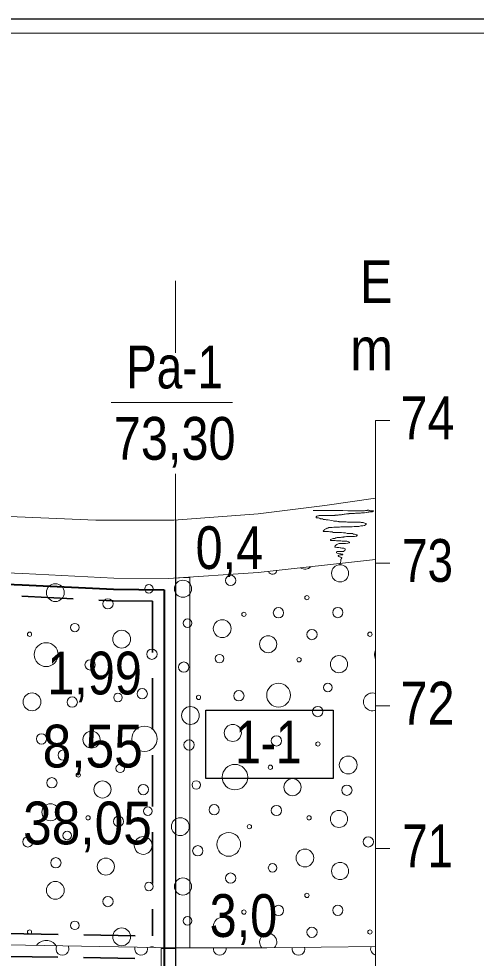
# Model space of a CAD drawing. Extents: x 640121 to 640955, y 6441885 to 6442246.
# Drawn here: x 640485.5 to 640517.6, y 6442180.3 to 6442246.2 of the extents above; entities that cross this region are included whole.
import ezdxf
from ezdxf.enums import TextEntityAlignment as Align

# ---------------------------------------------------------------- set-up
doc = ezdxf.new("R2010")
doc.units = 0
doc.header["$LTSCALE"] = 1.2
doc.linetypes.add('MEDIUM_DASHED', pattern=[4.5, 3, -1.5])
for name, color, linetype, lineweight in [('30', 7, 'Continuous', 13), ('31', 7, 'Continuous', 13), ('32', 7, 'Continuous', 13), ('33', 7, 'Continuous', 13), ('35', 7, 'Continuous', 35), ('40', 7, 'Continuous', 13), ('41', 7, 'Continuous', 13), ('42', 7, 'Continuous', 13), ('50', 7, 'Continuous', 13)]:
    doc.layers.add(name, color=color, linetype=linetype, lineweight=lineweight)

msp = doc.modelspace()

# ---------------------------------------------------------------- linework, layer by layer
at = {"layer": '30'}
for p, q in [((640510.5, 6442218), (640511.5, 6442218)), ((640510.5, 6442063), (640510.5, 6442218)), ((640510.5, 6442208), (640511.5, 6442208)), ((640510.5, 6442198), (640511.5, 6442198)), ((640510.5, 6442188), (640511.5, 6442188))]:
    msp.add_line(p, q, dxfattribs=at)
at = {"layer": '31'}
for points in [[(640362.7, 6442207.53), (640371.1, 6442207.66), (640378.91, 6442207.96), (640387.66, 6442208.39), (640395.09, 6442208.91), (640403.04, 6442209.13), (640410.1, 6442209.62), (640417.94, 6442210.22), (640426.11, 6442210.87), (640434.35, 6442211.6), (640443.55, 6442211.39), (640450.84, 6442211.31), (640460.31, 6442211.42), (640471.64, 6442211.39), (640480.39, 6442211.46), (640490.9, 6442211.02), (640496.37, 6442211.02), (640502.28, 6442211.46), (640506.95, 6442212.04), (640510.5, 6442212.56)], [(640362.55, 6442203.68), (640369.1, 6442203.88), (640381.31, 6442204.1), (640393.24, 6442204.9), (640403.15, 6442205.61), (640412.11, 6442206.42), (640420.43, 6442207.78), (640428.21, 6442208.95), (640434.36, 6442209.59), (640443.5, 6442209.32), (640451.09, 6442208.86), (640456.15, 6442208.6), (640464.23, 6442208.39), (640474.43, 6442207.96), (640479.86, 6442207.51), (640485.77, 6442207.28), (640492.16, 6442206.96), (640495.99, 6442206.92), (640502.28, 6442207.34), (640510.5, 6442208.25)], [(640361.87, 6442180.35), (640370.38, 6442181.71), (640378.83, 6442182.99), (640382.86, 6442183.28), (640390.58, 6442183.39), (640398.35, 6442183.34), (640407.42, 6442182.84), (640417.38, 6442182.24), (640426.85, 6442181.64), (640434.32, 6442181.74), (640441.06, 6442181.46), (640449.93, 6442181.22), (640459.93, 6442181.24), (640467.81, 6442181.49), (640476.37, 6442181.44), (640484.64, 6442181.24), (640496.4, 6442181.04), (640502.87, 6442181.04), (640510.5, 6442181.13)]]:
    msp.add_lwpolyline(points, dxfattribs=at)
at = {"layer": '32'}
msp.add_line((640491.97, 6442219.27), (640500.48, 6442219.27), dxfattribs=at)
at = {"layer": '32', "lineweight": 25}
msp.add_line((640496.47, 6442211.03), (640496.47, 6442143), dxfattribs=at)
at = {"layer": '33'}
for points in [[(640497.47, 6442181.04), (640497.47, 6442207), (640497.06, 6442207), (640496.47, 6442206.96), (640496.47, 6442181.04)], [(640495.47, 6442181), (640495.47, 6442149), (640496.42, 6442149), (640496.47, 6442149), (640496.47, 6442181), (640496.4, 6442181)]]:
    msp.add_lwpolyline(points, close=True, dxfattribs=at)
at = {"layer": '33', "lineweight": 25}
msp.add_lwpolyline([(640498.61, 6442197.69), (640507.53, 6442197.69), (640507.53, 6442192.91), (640498.61, 6442192.91)], close=True, dxfattribs=at)
at = {"layer": '35', "lineweight": 13}
for p, q in [((640496.47, 6442222.75), (640496.47, 6442227.8)), ((640496.47, 6442211.03), (640496.47, 6442214.27))]:
    msp.add_line(p, q, dxfattribs=at)
at = {"layer": '35', "lineweight": 40}
msp.add_line((640495.67, 6442206.13), (640495.67, 6442149.47), dxfattribs=at)
at = {"layer": '35', "linetype": 'MEDIUM_DASHED'}
msp.add_line((640494.87, 6442205.34), (640494.87, 6442181.87), dxfattribs=at)
at = {"layer": '35', "lineweight": 40}
msp.add_lwpolyline([(640481.18, 6442206.66), (640485.73, 6442206.48), (640492.14, 6442206.17), (640495.67, 6442206.13)], dxfattribs=at)
at = {"layer": '35', "linetype": 'MEDIUM_DASHED'}
for points in [[(640481.15, 6442205.86), (640485.7, 6442205.68), (640492.11, 6442205.37), (640494.87, 6442205.34)], [(640379.57, 6442183.85), (640382.82, 6442184.08), (640390.58, 6442184.19), (640398.38, 6442184.14), (640407.47, 6442183.64), (640417.43, 6442183.04), (640426.87, 6442182.44), (640434.33, 6442182.54), (640441.09, 6442182.26), (640449.94, 6442182.02), (640459.92, 6442182.04), (640467.8, 6442182.29), (640476.38, 6442182.24), (640484.66, 6442182.04), (640494.87, 6442181.87)], [(640377.97, 6442182.13), (640382.89, 6442182.48), (640390.58, 6442182.59), (640398.33, 6442182.54), (640407.37, 6442182.04), (640417.33, 6442181.44), (640426.83, 6442180.84), (640434.31, 6442180.94), (640441.03, 6442180.66), (640449.92, 6442180.42), (640459.94, 6442180.44), (640467.82, 6442180.69), (640476.36, 6442180.64), (640484.62, 6442180.44), (640494.87, 6442180.27)]]:
    msp.add_lwpolyline(points, dxfattribs=at)
at = {"layer": '40'}
for points in [[(640506.14, 6442211.69), (640506.2, 6442211.69), (640506.31, 6442211.69), (640506.42, 6442211.69), (640506.44, 6442211.7), (640506.55, 6442211.7), (640506.7, 6442211.7), (640507.03, 6442211.7), (640507.21, 6442211.7), (640507.24, 6442211.7), (640507.28, 6442211.7), (640507.35, 6442211.7), (640507.44, 6442211.7), (640507.54, 6442211.7), (640507.63, 6442211.7), (640507.69, 6442211.7), (640507.77, 6442211.7), (640507.84, 6442211.7), (640507.92, 6442211.7), (640508, 6442211.69), (640508.05, 6442211.69), (640508.12, 6442211.69), (640508.22, 6442211.69), (640508.55, 6442211.67), (640508.86, 6442211.66), (640508.96, 6442211.66), (640509.02, 6442211.66), (640509.06, 6442211.66), (640509.1, 6442211.66), (640509.18, 6442211.66), (640509.27, 6442211.67), (640509.32, 6442211.67), (640509.36, 6442211.67), (640509.38, 6442211.67), (640509.42, 6442211.67), (640509.49, 6442211.66), (640509.52, 6442211.66), (640509.57, 6442211.66), (640509.67, 6442211.67), (640509.73, 6442211.67), (640509.8, 6442211.69), (640509.84, 6442211.7), (640509.91, 6442211.7), (640509.94, 6442211.71), (640509.99, 6442211.71), (640510.04, 6442211.71), (640510.08, 6442211.7), (640510.11, 6442211.69), (640510.16, 6442211.67), (640510.2, 6442211.67)], [(640510.2, 6442211.67), (640510.24, 6442211.66), (640510.28, 6442211.66), (640510.33, 6442211.66), (640510.35, 6442211.64), (640510.33, 6442211.63), (640510.34, 6442211.64), (640510.3, 6442211.63), (640510.26, 6442211.61), (640510.2, 6442211.6), (640510.16, 6442211.6), (640510.11, 6442211.6), (640510.08, 6442211.59), (640510.04, 6442211.59), (640510.02, 6442211.57), (640509.96, 6442211.57), (640509.88, 6442211.55), (640509.85, 6442211.55), (640509.73, 6442211.54), (640509.68, 6442211.53), (640509.64, 6442211.53), (640509.6, 6442211.52), (640509.55, 6442211.52), (640509.51, 6442211.52), (640509.45, 6442211.51), (640509.42, 6442211.51), (640509.31, 6442211.51), (640509.25, 6442211.51), (640509.18, 6442211.51), (640509.09, 6442211.51), (640509.03, 6442211.49), (640508.98, 6442211.49), (640508.92, 6442211.48), (640508.86, 6442211.48), (640508.7, 6442211.48), (640508.66, 6442211.48), (640508.62, 6442211.47), (640508.55, 6442211.46), (640508.46, 6442211.45), (640508.37, 6442211.43), (640508.31, 6442211.43), (640508.23, 6442211.42), (640508.17, 6442211.42), (640508.12, 6442211.4), (640508.06, 6442211.4), (640508.04, 6442211.39), (640508, 6442211.39), (640507.94, 6442211.39), (640507.89, 6442211.37), (640507.86, 6442211.37), (640507.72, 6442211.36), (640507.68, 6442211.36)], [(640507.68, 6442211.36), (640507.64, 6442211.35), (640507.58, 6442211.35), (640507.54, 6442211.34), (640507.51, 6442211.34), (640507.47, 6442211.34), (640507.42, 6442211.34), (640507.38, 6442211.34), (640507.33, 6442211.34), (640507.26, 6442211.34), (640507.22, 6442211.34), (640507.16, 6442211.35), (640507.12, 6442211.35), (640507.09, 6442211.35), (640507.05, 6442211.35), (640507, 6442211.35), (640506.96, 6442211.35), (640506.88, 6442211.35), (640506.85, 6442211.35), (640506.81, 6442211.35), (640506.75, 6442211.35), (640506.72, 6442211.35), (640506.67, 6442211.35), (640506.63, 6442211.35), (640506.58, 6442211.35), (640506.54, 6442211.34), (640506.5, 6442211.31), (640506.45, 6442211.31), (640506.42, 6442211.3), (640506.39, 6442211.29), (640506.37, 6442211.28), (640506.34, 6442211.25), (640506.33, 6442211.22), (640506.34, 6442211.18), (640506.44, 6442211.17), (640506.5, 6442211.17), (640506.54, 6442211.15), (640506.58, 6442211.15), (640506.62, 6442211.13), (640506.64, 6442211.12), (640506.7, 6442211.12), (640506.75, 6442211.11), (640506.79, 6442211.1), (640506.86, 6442211.07), (640506.93, 6442211.06), (640507, 6442211.06), (640507.05, 6442211.05), (640507.1, 6442211.04), (640507.18, 6442211.03), (640507.29, 6442211.01)], [(640507.29, 6442211.01), (640507.44, 6442210.99), (640507.53, 6442210.97), (640507.59, 6442210.95), (640507.69, 6442210.94), (640507.78, 6442210.94), (640507.86, 6442210.93), (640507.92, 6442210.93), (640507.96, 6442210.91), (640508.05, 6442210.91), (640508.11, 6442210.91), (640508.19, 6442210.89), (640508.28, 6442210.89), (640508.35, 6442210.89), (640508.44, 6442210.89), (640508.53, 6442210.88), (640508.59, 6442210.88), (640508.62, 6442210.88), (640508.7, 6442210.88), (640508.77, 6442210.88), (640508.85, 6442210.88), (640508.95, 6442210.88), (640509.03, 6442210.88), (640509.09, 6442210.88), (640509.18, 6442210.88), (640509.21, 6442210.88), (640509.27, 6442210.88), (640509.33, 6442210.88), (640509.39, 6442210.87), (640509.45, 6442210.87), (640509.5, 6442210.86), (640509.63, 6442210.85), (640509.69, 6442210.82), (640509.75, 6442210.8), (640509.8, 6442210.79), (640509.84, 6442210.77), (640509.84, 6442210.74), (640509.82, 6442210.7), (640509.8, 6442210.69), (640509.78, 6442210.68), (640509.75, 6442210.65), (640509.7, 6442210.64), (640509.62, 6442210.62), (640509.48, 6442210.61), (640509.34, 6442210.58), (640509.27, 6442210.57), (640509.18, 6442210.57), (640509.09, 6442210.56), (640509, 6442210.56), (640508.86, 6442210.55), (640508.67, 6442210.55), (640508.5, 6442210.55)], [(640508.5, 6442210.55), (640508.42, 6442210.55), (640508.35, 6442210.55), (640508.26, 6442210.55), (640508.2, 6442210.55), (640508.14, 6442210.55), (640508.06, 6442210.55), (640507.98, 6442210.53), (640507.8, 6442210.53), (640507.71, 6442210.53), (640507.66, 6442210.52), (640507.58, 6442210.52), (640507.46, 6442210.5), (640507.33, 6442210.5), (640507.28, 6442210.49), (640507.22, 6442210.49), (640507.2, 6442210.47), (640507.16, 6442210.46), (640507.12, 6442210.46), (640507.09, 6442210.45), (640507.05, 6442210.44), (640507.03, 6442210.41), (640506.97, 6442210.38), (640506.93, 6442210.35), (640506.92, 6442210.33), (640506.88, 6442210.32), (640506.87, 6442210.29), (640506.85, 6442210.27), (640506.84, 6442210.25), (640506.86, 6442210.23), (640506.9, 6442210.23), (640506.96, 6442210.23), (640507, 6442210.23), (640507.11, 6442210.22), (640507.2, 6442210.21), (640507.29, 6442210.2), (640507.41, 6442210.19), (640507.47, 6442210.19), (640507.53, 6442210.16), (640507.59, 6442210.16), (640507.76, 6442210.16), (640507.89, 6442210.16), (640508, 6442210.15), (640508.11, 6442210.14), (640508.25, 6442210.13), (640508.4, 6442210.13), (640508.52, 6442210.09), (640508.6, 6442210.09), (640508.7, 6442210.09), (640508.78, 6442210.08)], [(640508.78, 6442210.08), (640508.83, 6442210.08), (640508.88, 6442210.07), (640508.96, 6442210.04), (640509.03, 6442210.03), (640509.08, 6442210.01), (640509.13, 6442209.99), (640509.19, 6442209.98), (640509.21, 6442209.97), (640509.22, 6442209.92), (640509.2, 6442209.91), (640509.18, 6442209.9), (640509.14, 6442209.89), (640509.02, 6442209.87), (640508.96, 6442209.87), (640508.92, 6442209.87), (640508.85, 6442209.87), (640508.77, 6442209.87), (640508.68, 6442209.86), (640508.64, 6442209.86), (640508.59, 6442209.86), (640508.46, 6442209.86), (640508.38, 6442209.84), (640508.35, 6442209.84), (640508.29, 6442209.84), (640508.25, 6442209.83), (640508.19, 6442209.83), (640508.11, 6442209.83), (640508.04, 6442209.81), (640507.95, 6442209.8), (640507.89, 6442209.79), (640507.86, 6442209.79), (640507.81, 6442209.79), (640507.77, 6442209.78), (640507.71, 6442209.78), (640507.7, 6442209.75), (640507.64, 6442209.74), (640507.62, 6442209.73), (640507.58, 6442209.73), (640507.53, 6442209.72), (640507.47, 6442209.71), (640507.41, 6442209.69), (640507.36, 6442209.67), (640507.34, 6442209.65), (640507.34, 6442209.6), (640507.38, 6442209.6), (640507.45, 6442209.6), (640507.54, 6442209.59), (640507.63, 6442209.59), (640507.68, 6442209.59), (640507.77, 6442209.57), (640507.83, 6442209.57)], [(640507.83, 6442209.57), (640507.86, 6442209.56), (640507.89, 6442209.56), (640507.95, 6442209.56), (640508.02, 6442209.56), (640508.06, 6442209.56), (640508.17, 6442209.55), (640508.25, 6442209.55), (640508.29, 6442209.55), (640508.34, 6442209.55), (640508.37, 6442209.55), (640508.43, 6442209.55), (640508.49, 6442209.54), (640508.54, 6442209.51), (640508.59, 6442209.5), (640508.64, 6442209.49), (640508.67, 6442209.48), (640508.67, 6442209.43), (640508.55, 6442209.41), (640508.4, 6442209.39), (640508.34, 6442209.39), (640508.23, 6442209.38), (640508.17, 6442209.38), (640508.1, 6442209.38), (640508.02, 6442209.37), (640507.95, 6442209.37), (640507.88, 6442209.35), (640507.8, 6442209.31), (640507.77, 6442209.29), (640507.72, 6442209.26), (640507.7, 6442209.24), (640507.68, 6442209.21), (640507.66, 6442209.18), (640507.64, 6442209.14), (640507.66, 6442209.13), (640507.71, 6442209.12), (640507.78, 6442209.09), (640507.92, 6442209.09), (640508.02, 6442209.08), (640508.08, 6442209.07), (640508.13, 6442209.06), (640508.2, 6442209.06), (640508.29, 6442209.05), (640508.38, 6442209.01), (640508.38, 6442208.96), (640508.37, 6442208.93), (640508.36, 6442208.9), (640508.29, 6442208.84), (640508.25, 6442208.83), (640508.19, 6442208.83), (640508.11, 6442208.83), (640508.02, 6442208.83), (640507.95, 6442208.83), (640507.87, 6442208.83), (640507.78, 6442208.81), (640507.77, 6442208.77), (640507.76, 6442208.75), (640507.77, 6442208.72), (640507.81, 6442208.71), (640507.93, 6442208.67), (640508.01, 6442208.66), (640508.06, 6442208.65), (640508.12, 6442208.64), (640508.18, 6442208.63), (640508.22, 6442208.6), (640508.19, 6442208.59), (640508.13, 6442208.59), (640508.06, 6442208.58), (640507.96, 6442208.57), (640507.93, 6442208.57), (640507.89, 6442208.55), (640507.89, 6442208.51), (640507.92, 6442208.48), (640507.94, 6442208.47), (640507.98, 6442208.45), (640508.02, 6442208.43), (640508.08, 6442208.42), (640508.13, 6442208.41), (640508.14, 6442208.36), (640508.12, 6442208.34), (640508.11, 6442208.3), (640508.08, 6442208.27), (640508.06, 6442208.24), (640508.06, 6442208.19), (640508.06, 6442208.15), (640508.06, 6442208.11), (640508.05, 6442208.07), (640508.05, 6442208.03), (640508.04, 6442208), (640508.02, 6442207.95), (640508.01, 6442207.92), (640508.01, 6442207.87), (640508.01, 6442207.86), (640508.01, 6442207.89)]]:
    msp.add_lwpolyline(points, dxfattribs=at)
at = {"layer": '41'}
for centre, radius in [((640508.017, 6442207.29), 0.6), ((640500.344, 6442206.794), 0.36), ((640488.05, 6442205.937), 0.624), ((640494.615, 6442206.204), 0.3), ((640497.001, 6442206.207), 0.6), ((640505.689, 6442205.583), 0.15), ((640491.742, 6442205.149), 0.36), ((640501.27, 6442204.416), 0.15), ((640503.693, 6442204.527), 0.36), ((640507.86, 6442204.537), 0.36), ((640489.419, 6442203.483), 0.3), ((640497.313, 6442203.792), 0.3), ((640499.752, 6442203.412), 0.624), ((640486.239, 6442203.018), 0.15), ((640492.701, 6442202.676), 0.624), ((640506.046, 6442202.995), 0.36), ((640510.108, 6442203.018), 0.15), ((640487.409, 6442201.59), 0.838), ((640502.977, 6442202.319), 0.6), ((640494.825, 6442201.619), 0.36), ((640490.488, 6442200.868), 0.36), ((640497.052, 6442200.716), 0.36), ((640499.56, 6442201.308), 0.3), ((640505.146, 6442201.23), 0.15), ((640507.939, 6442200.918), 0.6), ((640494.141, 6442198.853), 0.36), ((640500.921, 6442198.709), 0.36), ((640503.704, 6442198.749), 0.834), ((640507.162, 6442199.286), 0.3), ((640486.415, 6442198.281), 0.624), ((640489.234, 6442198.266), 0.36), ((640492.443, 6442198.587), 0.3), ((640498.09, 6442198.587), 0.15), ((640497.521, 6442197.323), 0.624), ((640506.449, 6442197.601), 0.36), ((640494.301, 6442195.691), 0.889), ((640500.493, 6442196.103), 0.6), ((640487.081, 6442195.68), 0.36), ((640490.583, 6442195.635), 0.6), ((640503.551, 6442195.542), 0.36), ((640497.427, 6442195.256), 0.36), ((640506.466, 6442195.326), 0.15), ((640488.6, 6442194.548), 0.36), ((640508.588, 6442193.855), 0.624), ((640492.599, 6442193.616), 0.3), ((640500.644, 6442193.002), 0.893), ((640503.13, 6442193.694), 0.15), ((640489.653, 6442193.151), 0.15), ((640487.808, 6442192.61), 0.36), ((640491.357, 6442192.14), 0.6), ((640494.219, 6442192.127), 0.36), ((640497.934, 6442192.452), 0.3), ((640504.681, 6442192.296), 0.6), ((640508.496, 6442192.085), 0.36), ((640487.712, 6442190.54), 0.6), ((640494.537, 6442190.615), 0.3), ((640499.189, 6442190.72), 0.36), ((640503.551, 6442190.664), 0.36), ((640507.939, 6442190.072), 0.6), ((640490.349, 6442190.15), 0.15), ((640492.478, 6442189.903), 0.36), ((640496.814, 6442189.534), 0.624), ((640505.845, 6442190.15), 0.15), ((640488.876, 6442188.908), 0.3), ((640501.657, 6442189.529), 0.15), ((640486.127, 6442188.462), 0.36), ((640494.212, 6442188.214), 0.624), ((640500.205, 6442188.292), 0.835), ((640509.996, 6442188.462), 0.36), ((640498.037, 6442187.839), 0.36), ((640505.551, 6442187.336), 0.624), ((640488.091, 6442187.001), 0.36), ((640491.591, 6442186.733), 0.6), ((640503.286, 6442186.652), 0.3), ((640508.017, 6442186.421), 0.6), ((640497.001, 6442185.338), 0.6), ((640500.344, 6442185.925), 0.36), ((640488.05, 6442185.068), 0.624), ((640494.615, 6442185.335), 0.3), ((640491.742, 6442184.28), 0.36), ((640505.689, 6442184.714), 0.15), ((640503.693, 6442183.658), 0.36), ((640507.86, 6442183.668), 0.36), ((640497.313, 6442182.923), 0.3), ((640501.27, 6442183.547), 0.15), ((640489.419, 6442182.614), 0.3), ((640499.752, 6442182.543), 0.624), ((640486.239, 6442182.149), 0.15), ((640492.701, 6442181.807), 0.624), ((640506.046, 6442182.126), 0.36), ((640510.108, 6442182.149), 0.15)]:
    msp.add_circle(centre, radius, dxfattribs=at)
for centre, radius, start, end in [((640505.551, 6442208.205), 0.624, 239.22074, 313.339), ((640503.286, 6442207.521), 0.3, 198.9483, 353.61143), ((640511.278, 6442201.59), 0.838, 157.34019, 202.65981), ((640510.284, 6442198.281), 0.624, 69.24909, 290.7509), ((640502.977, 6442181.45), 0.6, 318.22643, 222.59483), ((640487.409, 6442180.721), 0.838, 33.60568, 144.45228), ((640494.825, 6442180.75), 0.36, 62.07315, 115.9848)]:
    msp.add_arc(centre, radius, start, end, dxfattribs=at)
at = {"layer": '42'}
for centre, start, end in [((640488.548, 6442180.971), 151.68197, 26.37599), ((640494.063, 6442180.971), 164.45258, 13.60538), ((640499.578, 6442180.971), 170.57179, 9.42821), ((640505.094, 6442180.971), 167.90336, 13.42134), ((640510.609, 6442180.971), 159.4064, 256.57852)]:
    msp.add_arc(centre, 0.45, start, end, dxfattribs=at)
at = {"layer": '50', "lineweight": 25}
msp.add_lwpolyline([(640121.33, 6442246.16), (640955.23, 6442246.16), (640955.23, 6441889.4), (640121.33, 6441889.4)], close=True, dxfattribs=at)
at = {"layer": '50'}
msp.add_lwpolyline([(640122.33, 6442245.16), (640954.23, 6442245.16), (640954.23, 6441890.4), (640122.33, 6441890.4)], close=True, dxfattribs=at)

# ---------------------------------------------------------------- texts
at = {"layer": '30'}
for s, width, p in [('E', 0.85, (640510.55, 6442226.24)), ('m', 0.9, (640510.235, 6442221.51)), ('74', 0.85, (640514.15, 6442216.69)), ('73', 0.8, (640514.15, 6442206.69)), ('72', 0.85, (640514.15, 6442196.69)), ('71', 0.8, (640514.155, 6442186.69))]:
    msp.add_text(s, height=3, dxfattribs=dict(at, width=width)).set_placement(p, align=Align.CENTER)
at = {"layer": '32'}
for s, width, p in [('Pa-1', 0.8, (640496.41, 6442220.25)), ('73,30', 0.85, (640496.42, 6442215.25)), ('0,4', 0.85, (640500.255, 6442207.59)), ('1,99', 0.85, (640490.8, 6442198.8)), ('38,05', 0.9, (640490.305, 6442188.29)), ('3,0', 0.85, (640501.24, 6442181.8))]:
    msp.add_text(s, height=3, dxfattribs=dict(at, width=width)).set_placement(p, align=Align.CENTER)
at = {"layer": '33'}
for s, width, p in [('8,55', 0.9, (640490.67, 6442193.68)), ('1-1', 0.8, (640502.99, 6442193.96))]:
    msp.add_text(s, height=3, dxfattribs=dict(at, width=width)).set_placement(p, align=Align.CENTER)

doc.saveas('drawing.dxf')
